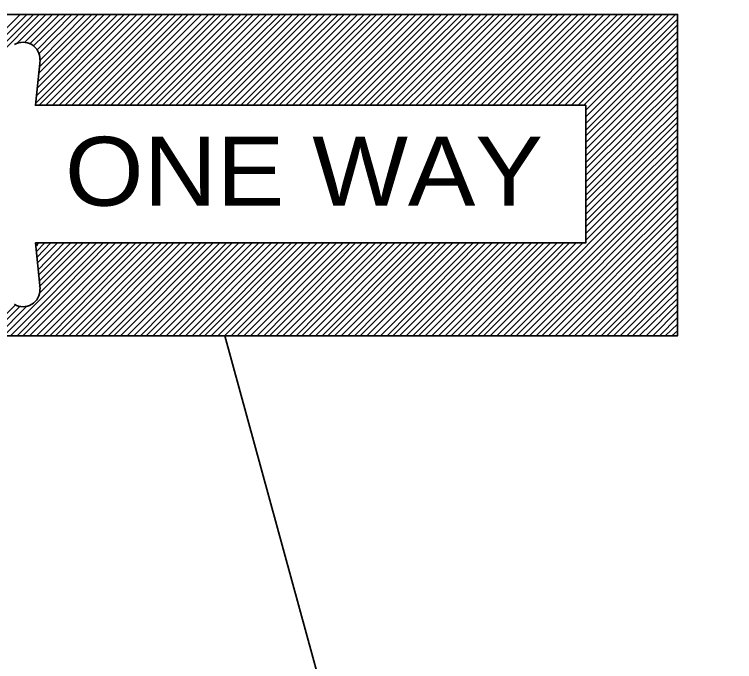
# Model space of a CAD drawing. Extents: x -133 to 547, y -328 to 112.
# Drawn here: x -38.04 to -22.96, y -13.45 to 0.08 of the extents above; entities that cross this region are included whole.
import ezdxf
from ezdxf.enums import TextEntityAlignment as Align

# ---------------------------------------------------------------- set-up
doc = ezdxf.new("R2010")
doc.units = 0
doc.header["$LTSCALE"] = 0.8
doc.layers.add('1', color=7, linetype='Continuous', lineweight=35)

msp = doc.modelspace()

# ---------------------------------------------------------------- linework, layer by layer
at = {"layer": '1'}
for p, q in [((-42.3959, -4.3959), (-37.9159, 0.0841)), ((-42.3959, -4.5359), (-37.7759, 0.0841)), ((-42.3959, -4.6759), (-37.6359, 0.0841)), ((-42.3959, -4.8159), (-37.5159, 0.0841)), ((-42.3959, -4.3959), (-37.9159, 0.0841)), ((-42.3959, -4.5359), (-37.7759, 0.0841)), ((-42.3959, -4.6759), (-37.6359, 0.0841)), ((-42.3959, -4.8159), (-37.5159, 0.0841)), ((-37.9759, -0.5159), (-37.3759, 0.0841)), ((-37.9759, -0.5159), (-37.3759, 0.0841)), ((-37.8159, -0.4959), (-37.2359, 0.0841)), ((-37.8159, -0.4959), (-37.2359, 0.0841)), ((-37.7159, -0.5359), (-37.0959, 0.0841)), ((-37.7159, -0.5359), (-37.0959, 0.0841)), ((-37.6359, -0.5759), (-36.9559, 0.0841)), ((-37.6359, -0.5759), (-36.9559, 0.0841)), ((-37.5759, -1.6159), (-35.8759, 0.0841)), ((-37.5759, -1.7559), (-35.7359, 0.0841)), ((-37.5759, -1.6159), (-35.8759, 0.0841)), ((-37.5759, -1.7559), (-35.7359, 0.0841)), ((-37.5559, -0.6559), (-36.8359, 0.0841)), ((-37.5559, -1.4559), (-36.0159, 0.0841)), ((-37.5559, -0.6559), (-36.8359, 0.0841)), ((-37.5559, -1.4559), (-36.0159, 0.0841)), ((-37.5359, -1.1559), (-36.2959, 0.0841)), ((-37.5359, -1.3159), (-36.1559, 0.0841)), ((-37.5359, -1.1559), (-36.2959, 0.0841)), ((-37.5359, -1.3159), (-36.1559, 0.0841)), ((-37.5159, -0.7359), (-36.6959, 0.0841)), ((-37.5159, -1.0159), (-36.4159, 0.0841)), ((-37.5159, -1.8159), (-35.6159, 0.0841)), ((-37.5159, -0.7359), (-36.6959, 0.0841)), ((-37.5159, -1.0159), (-36.4159, 0.0841)), ((-37.5159, -1.8159), (-35.6159, 0.0841)), ((-37.4959, -0.8759), (-36.5559, 0.0841)), ((-37.4959, -0.8759), (-36.5559, 0.0841)), ((-37.3759, -1.8159), (-35.4759, 0.0841)), ((-37.3759, -1.8159), (-35.4759, 0.0841)), ((-37.2359, -1.8159), (-35.3359, 0.0841)), ((-37.2359, -1.8159), (-35.3359, 0.0841)), ((-37.0959, -1.8159), (-35.1959, 0.0841)), ((-37.0959, -1.8159), (-35.1959, 0.0841)), ((-36.9759, -1.8159), (-35.0559, 0.0841)), ((-36.9759, -1.8159), (-35.0559, 0.0841)), ((-36.8359, -1.8159), (-34.9359, 0.0841)), ((-36.8359, -1.8159), (-34.9359, 0.0841)), ((-36.6959, -1.8159), (-34.7959, 0.0841)), ((-36.6959, -1.8159), (-34.7959, 0.0841)), ((-36.5559, -1.8159), (-34.6559, 0.0841)), ((-36.5559, -1.8159), (-34.6559, 0.0841)), ((-36.4159, -1.8159), (-34.5159, 0.0841)), ((-36.4159, -1.8159), (-34.5159, 0.0841)), ((-36.2959, -1.8159), (-34.3959, 0.0841)), ((-36.2959, -1.8159), (-34.3959, 0.0841)), ((-36.1559, -1.8159), (-34.2559, 0.0841)), ((-36.1559, -1.8159), (-34.2559, 0.0841)), ((-36.0159, -1.8159), (-34.1159, 0.0841)), ((-36.0159, -1.8159), (-34.1159, 0.0841)), ((-35.8759, -1.8159), (-33.9759, 0.0841)), ((-35.8759, -1.8159), (-33.9759, 0.0841)), ((-35.7359, -1.8159), (-33.8359, 0.0841)), ((-35.7359, -1.8159), (-33.8359, 0.0841)), ((-35.6159, -1.8159), (-33.7159, 0.0841)), ((-35.6159, -1.8159), (-33.7159, 0.0841)), ((-35.4759, -1.8159), (-33.5759, 0.0841)), ((-35.4759, -1.8159), (-33.5759, 0.0841)), ((-35.3359, -1.8159), (-33.4359, 0.0841)), ((-35.3359, -1.8159), (-33.4359, 0.0841)), ((-35.1959, -1.8159), (-33.2959, 0.0841)), ((-35.1959, -1.8159), (-33.2959, 0.0841)), ((-35.0759, -1.8159), (-33.1559, 0.0841)), ((-35.0759, -1.8159), (-33.1559, 0.0841)), ((-34.9359, -1.8159), (-33.0359, 0.0841)), ((-34.9359, -1.8159), (-33.0359, 0.0841)), ((-34.7959, -1.8159), (-32.8959, 0.0841)), ((-34.7959, -1.8159), (-32.8959, 0.0841)), ((-34.6559, -1.8159), (-32.7559, 0.0841)), ((-34.6559, -1.8159), (-32.7559, 0.0841)), ((-34.5159, -1.8159), (-32.6159, 0.0841)), ((-34.5159, -1.8159), (-32.6159, 0.0841)), ((-34.3959, -1.8159), (-32.4759, 0.0841)), ((-34.3959, -1.8159), (-32.4759, 0.0841)), ((-34.2559, -1.8159), (-32.3559, 0.0841)), ((-34.2559, -1.8159), (-32.3559, 0.0841)), ((-34.1159, -1.8159), (-32.2159, 0.0841)), ((-34.1159, -1.8159), (-32.2159, 0.0841)), ((-33.9759, -1.8159), (-32.0759, 0.0841)), ((-33.9759, -1.8159), (-32.0759, 0.0841)), ((-33.8359, -1.8159), (-31.9359, 0.0841)), ((-33.8359, -1.8159), (-31.9359, 0.0841)), ((-33.7159, -1.8159), (-31.8159, 0.0841)), ((-33.7159, -1.8159), (-31.8159, 0.0841)), ((-33.5759, -1.8159), (-31.6759, 0.0841)), ((-33.5759, -1.8159), (-31.6759, 0.0841)), ((-33.4359, -1.8159), (-31.5359, 0.0841)), ((-33.4359, -1.8159), (-31.5359, 0.0841)), ((-33.2959, -1.8159), (-31.3959, 0.0841)), ((-33.2959, -1.8159), (-31.3959, 0.0841)), ((-33.1759, -1.8159), (-31.2559, 0.0841)), ((-33.1759, -1.8159), (-31.2559, 0.0841)), ((-33.0359, -1.8159), (-31.1359, 0.0841)), ((-33.0359, -1.8159), (-31.1359, 0.0841)), ((-32.8959, -1.8159), (-30.9959, 0.0841)), ((-32.8959, -1.8159), (-30.9959, 0.0841)), ((-32.7559, -1.8159), (-30.8559, 0.0841)), ((-32.7559, -1.8159), (-30.8559, 0.0841)), ((-32.6159, -1.8159), (-30.7159, 0.0841)), ((-32.6159, -1.8159), (-30.7159, 0.0841)), ((-32.4959, -1.8159), (-30.5759, 0.0841)), ((-32.4959, -1.8159), (-30.5759, 0.0841)), ((-32.3559, -1.8159), (-30.4559, 0.0841)), ((-32.3559, -1.8159), (-30.4559, 0.0841)), ((-32.2159, -1.8159), (-30.3159, 0.0841)), ((-32.2159, -1.8159), (-30.3159, 0.0841)), ((-32.0759, -1.8159), (-30.1759, 0.0841)), ((-32.0759, -1.8159), (-30.1759, 0.0841)), ((-31.9359, -1.8159), (-30.0359, 0.0841)), ((-31.9359, -1.8159), (-30.0359, 0.0841)), ((-31.8159, -1.8159), (-29.9159, 0.0841)), ((-31.8159, -1.8159), (-29.9159, 0.0841)), ((-31.6759, -1.8159), (-29.7759, 0.0841)), ((-31.6759, -1.8159), (-29.7759, 0.0841)), ((-31.5359, -1.8159), (-29.6359, 0.0841)), ((-31.5359, -1.8159), (-29.6359, 0.0841)), ((-31.3959, -1.8159), (-29.4959, 0.0841)), ((-31.3959, -1.8159), (-29.4959, 0.0841)), ((-31.2559, -1.8159), (-29.3559, 0.0841)), ((-31.2559, -1.8159), (-29.3559, 0.0841)), ((-31.1359, -1.8159), (-29.2359, 0.0841)), ((-31.1359, -1.8159), (-29.2359, 0.0841)), ((-30.9959, -1.8159), (-29.0959, 0.0841)), ((-30.9959, -1.8159), (-29.0959, 0.0841)), ((-30.8559, -1.8159), (-28.9559, 0.0841)), ((-30.8559, -1.8159), (-28.9559, 0.0841)), ((-30.7159, -1.8159), (-28.8159, 0.0841)), ((-30.7159, -1.8159), (-28.8159, 0.0841)), ((-30.5959, -1.8159), (-28.6759, 0.0841)), ((-30.5959, -1.8159), (-28.6759, 0.0841)), ((-30.4559, -1.8159), (-28.5559, 0.0841)), ((-30.4559, -1.8159), (-28.5559, 0.0841)), ((-30.3159, -1.8159), (-28.4159, 0.0841)), ((-30.3159, -1.8159), (-28.4159, 0.0841)), ((-30.1759, -1.8159), (-28.2759, 0.0841)), ((-30.1759, -1.8159), (-28.2759, 0.0841)), ((-30.0359, -1.8159), (-28.1359, 0.0841)), ((-30.0359, -1.8159), (-28.1359, 0.0841)), ((-29.9159, -1.8159), (-27.9959, 0.0841)), ((-29.9159, -1.8159), (-27.9959, 0.0841)), ((-29.7759, -1.8159), (-27.8759, 0.0841)), ((-29.7759, -1.8159), (-27.8759, 0.0841)), ((-29.6359, -1.8159), (-27.7359, 0.0841)), ((-29.6359, -1.8159), (-27.7359, 0.0841)), ((-29.4959, -1.8159), (-27.5959, 0.0841)), ((-29.4959, -1.8159), (-27.5959, 0.0841)), ((-29.3559, -1.8159), (-27.4559, 0.0841)), ((-29.3559, -1.8159), (-27.4559, 0.0841)), ((-29.2359, -1.8159), (-27.3359, 0.0841)), ((-29.2359, -1.8159), (-27.3359, 0.0841)), ((-29.0959, -1.8159), (-27.1959, 0.0841)), ((-29.0959, -1.8159), (-27.1959, 0.0841)), ((-28.9559, -1.8159), (-27.0559, 0.0841)), ((-28.9559, -1.8159), (-27.0559, 0.0841)), ((-28.8159, -1.8159), (-26.9159, 0.0841)), ((-28.8159, -1.8159), (-26.9159, 0.0841)), ((-28.6759, -1.8159), (-26.7759, 0.0841)), ((-28.6759, -1.8159), (-26.7759, 0.0841)), ((-28.5559, -1.8159), (-26.6559, 0.0841)), ((-28.5559, -1.8159), (-26.6559, 0.0841)), ((-28.4159, -1.8159), (-26.5159, 0.0841)), ((-28.4159, -1.8159), (-26.5159, 0.0841)), ((-28.2759, -1.8159), (-26.3759, 0.0841)), ((-28.2759, -1.8159), (-26.3759, 0.0841)), ((-28.1359, -1.8159), (-26.2359, 0.0841)), ((-28.1359, -1.8159), (-26.2359, 0.0841)), ((-28.0159, -1.8159), (-26.0959, 0.0841)), ((-28.0159, -1.8159), (-26.0959, 0.0841)), ((-27.8759, -1.8159), (-25.9759, 0.0841)), ((-27.8759, -1.8159), (-25.9759, 0.0841)), ((-27.7359, -1.8159), (-25.8359, 0.0841)), ((-27.7359, -1.8159), (-25.8359, 0.0841)), ((-27.5959, -1.8159), (-25.6959, 0.0841)), ((-27.5959, -1.8159), (-25.6959, 0.0841)), ((-27.4559, -1.8159), (-25.5559, 0.0841)), ((-27.4559, -1.8159), (-25.5559, 0.0841)), ((-27.3359, -1.8159), (-25.4159, 0.0841)), ((-27.3359, -1.8159), (-25.4159, 0.0841)), ((-27.1959, -1.8159), (-25.2959, 0.0841)), ((-27.1959, -1.8159), (-25.2959, 0.0841)), ((-27.0559, -1.8159), (-25.1559, 0.0841)), ((-27.0559, -1.8159), (-25.1559, 0.0841)), ((-26.9159, -1.8159), (-25.0159, 0.0841)), ((-26.9159, -1.8159), (-25.0159, 0.0841)), ((-26.7759, -1.8159), (-24.8759, 0.0841)), ((-26.7759, -1.8159), (-24.8759, 0.0841)), ((-26.6559, -1.8159), (-24.7559, 0.0841)), ((-26.6559, -1.8159), (-24.7559, 0.0841)), ((-26.5159, -1.8159), (-24.6159, 0.0841)), ((-26.5159, -1.8159), (-24.6159, 0.0841)), ((-26.3759, -1.8159), (-24.4759, 0.0841)), ((-26.3759, -1.8159), (-24.4759, 0.0841)), ((-26.2359, -1.8159), (-24.3359, 0.0841)), ((-26.2359, -1.8159), (-24.3359, 0.0841)), ((-26.1159, -1.8159), (-24.1959, 0.0841)), ((-26.1159, -1.8159), (-24.1959, 0.0841)), ((-26.0759, -1.9159), (-24.1559, -0.0159)), ((-26.0759, -1.9159), (-24.1559, -0.0159)), ((-26.0759, -2.0559), (-24.1559, -0.1359)), ((-26.0759, -2.0559), (-24.1559, -0.1359)), ((-26.0759, -2.1959), (-24.1559, -0.2759)), ((-26.0759, -2.1959), (-24.1559, -0.2759)), ((-26.0759, -2.3359), (-24.1559, -0.4159)), ((-26.0759, -2.3359), (-24.1559, -0.4159)), ((-26.0759, -2.4559), (-24.1559, -0.5559)), ((-26.0759, -2.4559), (-24.1559, -0.5559)), ((-26.0759, -2.5959), (-24.1559, -0.6959)), ((-26.0759, -2.5959), (-24.1559, -0.6959)), ((-26.0759, -2.7359), (-24.1559, -0.8159)), ((-26.0759, -2.7359), (-24.1559, -0.8159)), ((-26.0759, -2.8759), (-24.1559, -0.9559)), ((-26.0759, -2.8759), (-24.1559, -0.9559)), ((-26.0759, -3.0159), (-24.1559, -1.0959)), ((-26.0759, -3.0159), (-24.1559, -1.0959)), ((-26.0759, -3.1359), (-24.1559, -1.2359)), ((-26.0759, -3.1359), (-24.1559, -1.2359)), ((-26.0759, -3.2759), (-24.1559, -1.3759)), ((-26.0759, -3.2759), (-24.1559, -1.3759)), ((-26.0759, -3.4159), (-24.1559, -1.4959)), ((-26.0759, -3.4159), (-24.1559, -1.4959)), ((-26.0759, -3.5559), (-24.1559, -1.6359)), ((-26.0759, -3.5559), (-24.1559, -1.6359)), ((-26.0759, -3.6959), (-24.1559, -1.7759)), ((-26.0759, -3.6959), (-24.1559, -1.7759)), ((-26.0759, -3.8159), (-24.1559, -1.9159)), ((-26.0759, -3.8159), (-24.1559, -1.9159)), ((-26.0759, -3.9559), (-24.1559, -2.0559)), ((-26.0759, -3.9559), (-24.1559, -2.0559)), ((-26.0759, -4.0959), (-24.1559, -2.1759)), ((-26.0759, -4.0959), (-24.1559, -2.1759)), ((-26.0759, -4.2359), (-24.1559, -2.3159)), ((-26.0759, -4.2359), (-24.1559, -2.3159)), ((-26.0759, -4.3559), (-24.1559, -2.4559)), ((-26.0759, -4.3559), (-24.1559, -2.4559)), ((-26.0759, -4.4959), (-24.1559, -2.5959)), ((-26.0759, -4.4959), (-24.1559, -2.5959)), ((-27.9359, -6.6359), (-24.1559, -2.8559)), ((-27.9359, -6.6359), (-24.1559, -2.8559)), ((-26.0759, -4.6359), (-24.1559, -2.7159)), ((-26.0759, -4.6359), (-24.1559, -2.7159)), ((-27.7959, -6.6359), (-24.1559, -2.9959)), ((-27.7959, -6.6359), (-24.1559, -2.9959)), ((-27.6559, -6.6359), (-24.1559, -3.1359)), ((-27.6559, -6.6359), (-24.1559, -3.1359)), ((-27.5359, -6.6359), (-24.1559, -3.2759)), ((-27.5359, -6.6359), (-24.1559, -3.2759)), ((-27.3959, -6.6359), (-24.1559, -3.3959)), ((-27.3959, -6.6359), (-24.1559, -3.3959)), ((-27.2559, -6.6359), (-24.1559, -3.5359)), ((-27.2559, -6.6359), (-24.1559, -3.5359)), ((-27.1159, -6.6359), (-24.1559, -3.6759)), ((-27.1159, -6.6359), (-24.1559, -3.6759)), ((-26.9959, -6.6359), (-24.1559, -3.8159)), ((-26.9959, -6.6359), (-24.1559, -3.8159)), ((-26.8559, -6.6359), (-24.1559, -3.9559)), ((-26.8559, -6.6359), (-24.1559, -3.9559)), ((-26.7159, -6.6359), (-24.1559, -4.0759)), ((-26.7159, -6.6359), (-24.1559, -4.0759)), ((-26.5759, -6.6359), (-24.1559, -4.2159)), ((-26.5759, -6.6359), (-24.1559, -4.2159)), ((-26.4359, -6.6359), (-24.1559, -4.3559)), ((-26.4359, -6.6359), (-24.1559, -4.3559)), ((-26.3159, -6.6359), (-24.1559, -4.4959)), ((-26.3159, -6.6359), (-24.1559, -4.4959)), ((-26.1759, -6.6359), (-24.1559, -4.6359)), ((-26.1759, -6.6359), (-24.1559, -4.6359)), ((-38.2559, -6.6359), (-36.3159, -4.6959)), ((-38.2559, -6.6359), (-36.3159, -4.6959)), ((-38.1159, -6.6359), (-36.1759, -4.6959)), ((-38.1159, -6.6359), (-36.1759, -4.6959)), ((-37.9759, -6.6359), (-36.0559, -4.6959)), ((-37.9759, -6.6359), (-36.0559, -4.6959)), ((-37.8559, -6.6359), (-35.9159, -4.6959)), ((-37.8559, -6.6359), (-35.9159, -4.6959)), ((-37.7159, -6.6359), (-35.7759, -4.6959)), ((-37.7159, -6.6359), (-35.7759, -4.6959)), ((-37.5759, -4.7559), (-37.5359, -4.6959)), ((-37.5759, -4.8759), (-37.3959, -4.6959)), ((-37.5759, -6.6359), (-35.6359, -4.6959)), ((-37.5759, -4.7559), (-37.5359, -4.6959)), ((-37.5759, -4.8759), (-37.3959, -4.6959)), ((-37.5759, -6.6359), (-35.6359, -4.6959)), ((-37.5559, -4.9959), (-37.2759, -4.6959)), ((-37.5559, -5.1159), (-37.1359, -4.6959)), ((-37.5559, -4.9959), (-37.2759, -4.6959)), ((-37.5559, -5.1159), (-37.1359, -4.6959)), ((-37.5359, -5.2559), (-36.9959, -4.6959)), ((-37.5359, -5.3759), (-36.8559, -4.6959)), ((-37.5359, -5.2559), (-36.9959, -4.6959)), ((-37.5359, -5.3759), (-36.8559, -4.6959)), ((-37.5159, -5.4959), (-36.7159, -4.6959)), ((-37.5159, -5.6159), (-36.5959, -4.6959)), ((-37.5159, -5.7559), (-36.4559, -4.6959)), ((-37.5159, -5.4959), (-36.7159, -4.6959)), ((-37.5159, -5.6159), (-36.5959, -4.6959)), ((-37.5159, -5.7559), (-36.4559, -4.6959)), ((-37.4359, -6.6359), (-35.4959, -4.6959)), ((-37.4359, -6.6359), (-35.4959, -4.6959)), ((-37.2959, -6.6359), (-35.3759, -4.6959)), ((-37.2959, -6.6359), (-35.3759, -4.6959)), ((-37.1759, -6.6359), (-35.2359, -4.6959)), ((-37.1759, -6.6359), (-35.2359, -4.6959)), ((-37.0359, -6.6359), (-35.0959, -4.6959)), ((-37.0359, -6.6359), (-35.0959, -4.6959)), ((-36.8959, -6.6359), (-34.9559, -4.6959)), ((-36.8959, -6.6359), (-34.9559, -4.6959)), ((-36.7559, -6.6359), (-34.8159, -4.6959)), ((-36.7559, -6.6359), (-34.8159, -4.6959)), ((-36.6359, -6.6359), (-34.6959, -4.6959)), ((-36.6359, -6.6359), (-34.6959, -4.6959)), ((-36.4959, -6.6359), (-34.5559, -4.6959)), ((-36.4959, -6.6359), (-34.5559, -4.6959)), ((-36.3559, -6.6359), (-34.4159, -4.6959)), ((-36.3559, -6.6359), (-34.4159, -4.6959)), ((-36.2159, -6.6359), (-34.2759, -4.6959)), ((-36.2159, -6.6359), (-34.2759, -4.6959)), ((-36.0759, -6.6359), (-34.1359, -4.6959)), ((-36.0759, -6.6359), (-34.1359, -4.6959)), ((-35.9559, -6.6359), (-34.0159, -4.6959)), ((-35.9559, -6.6359), (-34.0159, -4.6959)), ((-35.8159, -6.6359), (-33.8759, -4.6959)), ((-35.8159, -6.6359), (-33.8759, -4.6959)), ((-35.6759, -6.6359), (-33.7359, -4.6959)), ((-35.6759, -6.6359), (-33.7359, -4.6959)), ((-35.5359, -6.6359), (-33.5959, -4.6959)), ((-35.5359, -6.6359), (-33.5959, -4.6959)), ((-35.3959, -6.6359), (-33.4759, -4.6959)), ((-35.3959, -6.6359), (-33.4759, -4.6959)), ((-35.2759, -6.6359), (-33.3359, -4.6959)), ((-35.2759, -6.6359), (-33.3359, -4.6959)), ((-35.1359, -6.6359), (-33.1959, -4.6959)), ((-35.1359, -6.6359), (-33.1959, -4.6959)), ((-34.9959, -6.6359), (-33.0559, -4.6959)), ((-34.9959, -6.6359), (-33.0559, -4.6959)), ((-34.8559, -6.6359), (-32.9159, -4.6959)), ((-34.8559, -6.6359), (-32.9159, -4.6959)), ((-34.7159, -6.6359), (-32.7959, -4.6959)), ((-34.7159, -6.6359), (-32.7959, -4.6959)), ((-34.5959, -6.6359), (-32.6559, -4.6959)), ((-34.5959, -6.6359), (-32.6559, -4.6959)), ((-34.4559, -6.6359), (-32.5159, -4.6959)), ((-34.4559, -6.6359), (-32.5159, -4.6959)), ((-34.3159, -6.6359), (-32.3759, -4.6959)), ((-34.3159, -6.6359), (-32.3759, -4.6959)), ((-34.1759, -6.6359), (-32.2359, -4.6959)), ((-34.1759, -6.6359), (-32.2359, -4.6959)), ((-34.0559, -6.6359), (-32.1159, -4.6959)), ((-34.0559, -6.6359), (-32.1159, -4.6959)), ((-33.9159, -6.6359), (-31.9759, -4.6959)), ((-33.9159, -6.6359), (-31.9759, -4.6959)), ((-33.7759, -6.6359), (-31.8359, -4.6959)), ((-33.7759, -6.6359), (-31.8359, -4.6959)), ((-33.6359, -6.6359), (-31.6959, -4.6959)), ((-33.6359, -6.6359), (-31.6959, -4.6959)), ((-33.4959, -6.6359), (-31.5559, -4.6959)), ((-33.4959, -6.6359), (-31.5559, -4.6959)), ((-33.3759, -6.6359), (-31.4359, -4.6959)), ((-33.3759, -6.6359), (-31.4359, -4.6959)), ((-33.2359, -6.6359), (-31.2959, -4.6959)), ((-33.2359, -6.6359), (-31.2959, -4.6959)), ((-33.0959, -6.6359), (-31.1559, -4.6959)), ((-33.0959, -6.6359), (-31.1559, -4.6959)), ((-32.9559, -6.6359), (-31.0159, -4.6959)), ((-32.9559, -6.6359), (-31.0159, -4.6959)), ((-32.8159, -6.6359), (-30.8959, -4.6959)), ((-32.8159, -6.6359), (-30.8959, -4.6959)), ((-32.6959, -6.6359), (-30.7559, -4.6959)), ((-32.6959, -6.6359), (-30.7559, -4.6959)), ((-32.5559, -6.6359), (-30.6159, -4.6959)), ((-32.5559, -6.6359), (-30.6159, -4.6959)), ((-32.4159, -6.6359), (-30.4759, -4.6959)), ((-32.4159, -6.6359), (-30.4759, -4.6959)), ((-32.2759, -6.6359), (-30.3359, -4.6959)), ((-32.2759, -6.6359), (-30.3359, -4.6959)), ((-32.1359, -6.6359), (-30.2159, -4.6959)), ((-32.1359, -6.6359), (-30.2159, -4.6959)), ((-32.0159, -6.6359), (-30.0759, -4.6959)), ((-32.0159, -6.6359), (-30.0759, -4.6959)), ((-31.8759, -6.6359), (-29.9359, -4.6959)), ((-31.8759, -6.6359), (-29.9359, -4.6959)), ((-31.7359, -6.6359), (-29.7959, -4.6959)), ((-31.7359, -6.6359), (-29.7959, -4.6959)), ((-31.5959, -6.6359), (-29.6559, -4.6959)), ((-31.5959, -6.6359), (-29.6559, -4.6959)), ((-31.4759, -6.6359), (-29.5359, -4.6959)), ((-31.4759, -6.6359), (-29.5359, -4.6959)), ((-31.3359, -6.6359), (-29.3959, -4.6959)), ((-31.3359, -6.6359), (-29.3959, -4.6959)), ((-31.1959, -6.6359), (-29.2559, -4.6959)), ((-31.1959, -6.6359), (-29.2559, -4.6959)), ((-31.0559, -6.6359), (-29.1159, -4.6959)), ((-31.0559, -6.6359), (-29.1159, -4.6959)), ((-30.9159, -6.6359), (-28.9959, -4.6959)), ((-30.9159, -6.6359), (-28.9959, -4.6959)), ((-30.7959, -6.6359), (-28.8559, -4.6959)), ((-30.7959, -6.6359), (-28.8559, -4.6959)), ((-30.6559, -6.6359), (-28.7159, -4.6959)), ((-30.6559, -6.6359), (-28.7159, -4.6959)), ((-30.5159, -6.6359), (-28.5759, -4.6959)), ((-30.5159, -6.6359), (-28.5759, -4.6959)), ((-30.3759, -6.6359), (-28.4359, -4.6959)), ((-30.3759, -6.6359), (-28.4359, -4.6959)), ((-30.2359, -6.6359), (-28.3159, -4.6959)), ((-30.2359, -6.6359), (-28.3159, -4.6959)), ((-30.1159, -6.6359), (-28.1759, -4.6959)), ((-30.1159, -6.6359), (-28.1759, -4.6959)), ((-29.9759, -6.6359), (-28.0359, -4.6959)), ((-29.9759, -6.6359), (-28.0359, -4.6959)), ((-29.8359, -6.6359), (-27.8959, -4.6959)), ((-29.8359, -6.6359), (-27.8959, -4.6959)), ((-29.6959, -6.6359), (-27.7559, -4.6959)), ((-29.6959, -6.6359), (-27.7559, -4.6959)), ((-29.5759, -6.6359), (-27.6359, -4.6959)), ((-29.5759, -6.6359), (-27.6359, -4.6959)), ((-29.4359, -6.6359), (-27.4959, -4.6959)), ((-29.4359, -6.6359), (-27.4959, -4.6959)), ((-29.2959, -6.6359), (-27.3559, -4.6959)), ((-29.2959, -6.6359), (-27.3559, -4.6959)), ((-29.1559, -6.6359), (-27.2159, -4.6959)), ((-29.1559, -6.6359), (-27.2159, -4.6959)), ((-29.0159, -6.6359), (-27.0759, -4.6959)), ((-29.0159, -6.6359), (-27.0759, -4.6959)), ((-28.8959, -6.6359), (-26.9559, -4.6959)), ((-28.8959, -6.6359), (-26.9559, -4.6959)), ((-28.7559, -6.6359), (-26.8159, -4.6959)), ((-28.7559, -6.6359), (-26.8159, -4.6959)), ((-28.6159, -6.6359), (-26.6759, -4.6959)), ((-28.6159, -6.6359), (-26.6759, -4.6959)), ((-28.4759, -6.6359), (-26.5359, -4.6959)), ((-28.4759, -6.6359), (-26.5359, -4.6959)), ((-28.3359, -6.6359), (-26.4159, -4.6959)), ((-28.3359, -6.6359), (-26.4159, -4.6959)), ((-28.2159, -6.6359), (-26.2759, -4.6959)), ((-28.2159, -6.6359), (-26.2759, -4.6959)), ((-28.0759, -6.6359), (-26.1359, -4.6959)), ((-28.0759, -6.6359), (-26.1359, -4.6959)), ((-26.0359, -6.6359), (-24.1559, -4.7559)), ((-26.0359, -6.6359), (-24.1559, -4.7559)), ((-25.8959, -6.6359), (-24.1559, -4.8959)), ((-25.8959, -6.6359), (-24.1559, -4.8959)), ((-25.7559, -6.6359), (-24.1559, -5.0359)), ((-25.7559, -6.6359), (-24.1559, -5.0359)), ((-25.6359, -6.6359), (-24.1559, -5.1759)), ((-25.6359, -6.6359), (-24.1559, -5.1759)), ((-25.4959, -6.6359), (-24.1559, -5.2959)), ((-25.4959, -6.6359), (-24.1559, -5.2959)), ((-25.3559, -6.6359), (-24.1559, -5.4359)), ((-25.3559, -6.6359), (-24.1559, -5.4359)), ((-25.2159, -6.6359), (-24.1559, -5.5759)), ((-25.2159, -6.6359), (-24.1559, -5.5759)), ((-25.0959, -6.6359), (-24.1559, -5.7159)), ((-25.0959, -6.6359), (-24.1559, -5.7159)), ((-24.9559, -6.6359), (-24.1559, -5.8559)), ((-24.9559, -6.6359), (-24.1559, -5.8559)), ((-38.6559, -6.6359), (-38.0159, -5.9959)), ((-38.6559, -6.6359), (-38.0159, -5.9959)), ((-38.5359, -6.6359), (-37.9159, -6.0159)), ((-38.5359, -6.6359), (-37.9159, -6.0159)), ((-38.3959, -6.6359), (-37.7759, -6.0159)), ((-38.3959, -6.6359), (-37.7759, -6.0159)), ((-24.8159, -6.6359), (-24.1559, -5.9759)), ((-24.8159, -6.6359), (-24.1559, -5.9759)), ((-24.6759, -6.6359), (-24.1559, -6.1159)), ((-24.6759, -6.6359), (-24.1559, -6.1159)), ((-24.5359, -6.6359), (-24.1559, -6.2559)), ((-24.5359, -6.6359), (-24.1559, -6.2559)), ((-24.4159, -6.6359), (-24.1559, -6.3959)), ((-24.4159, -6.6359), (-24.1559, -6.3959)), ((-24.2759, -6.6359), (-24.1559, -6.5359)), ((-24.2759, -6.6359), (-24.1559, -6.5359))]:
    msp.add_line(p, q, dxfattribs=at)
msp.add_lwpolyline([(-42.3959, 0.0841), (-24.1559, 0.0841), (-24.1559, -6.6359), (-42.3959, -6.6359)], close=True, dxfattribs=at)
msp.add_lwpolyline([(-42.3959, 0.0841), (-24.1559, 0.0841), (-24.1559, -6.6359), (-42.3959, -6.6359)], close=True, dxfattribs=at)
for points in [[(-37.4959, -0.8759), (-37.5959, -1.8159), (-26.0759, -1.8159), (-26.0759, -4.6959), (-37.5959, -4.6959), (-37.4959, -5.6559)], [(-37.4959, -0.8759), (-37.5959, -1.8159), (-26.0759, -1.8159), (-26.0759, -4.6959), (-37.5959, -4.6959), (-37.4959, -5.6559)], [(-22.9616, -16.3643), (-28.9851, -23.5949), (-33.6299, -6.6359)]]:
    msp.add_lwpolyline(points, dxfattribs=at)
for centre, start, end in [((-37.8536, -0.8462), 356.63551, 121.23355), ((-37.8536, -0.8462), 356.63551, 121.23355), ((-37.8536, -5.6798), 238.76645, 3.36449), ((-37.8536, -5.6798), 238.76645, 3.36449)]:
    msp.add_arc(centre, 0.3492, start, end, dxfattribs=at)

# ---------------------------------------------------------------- texts
at = {"layer": '1', "width": 1.1}
for p in [(-31.9759, -3.9159), (-31.9756, -3.9159)]:
    msp.add_text('ONE WAY', height=1.44, dxfattribs=at).set_placement(p, align=Align.CENTER)

doc.saveas('drawing.dxf')
